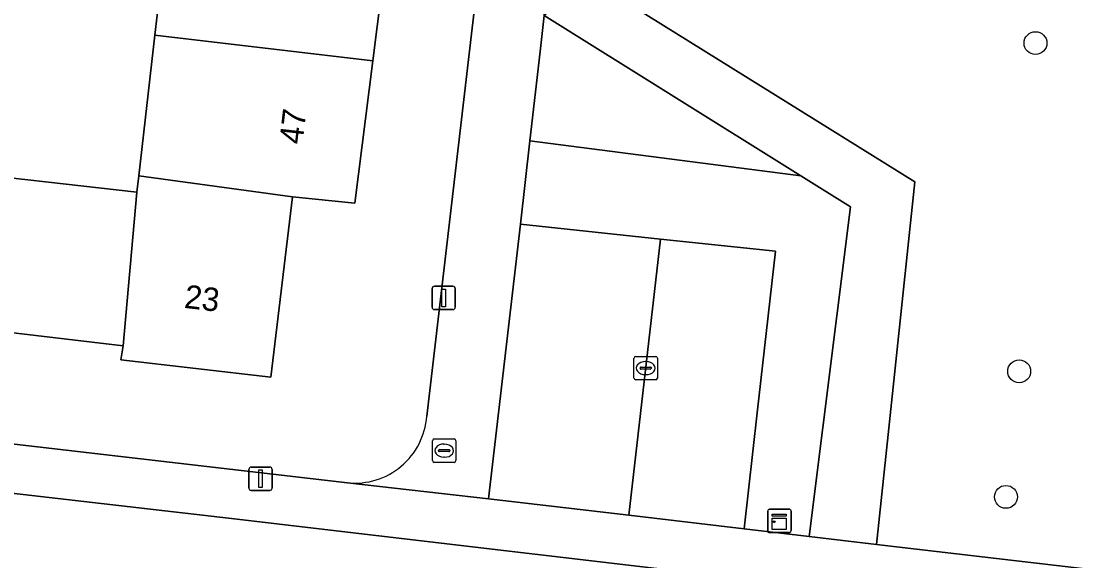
# Model space of a CAD drawing. Extents: x 161241 to 161758, y 384138 to 384885.
# Drawn here: x 161373.53 to 161418.62, y 384429.23 to 384452.33 of the extents above; entities that cross this region are included whole.
import ezdxf

# ---------------------------------------------------------------- set-up
doc = ezdxf.new("R2010")
doc.units = 0
for name, color, linetype in [('IMGEO_Boom', 7, 'Continuous'), ('IMGEO_Brandkraan', 7, 'Continuous'), ('IMGEO_Erf', 7, 'Continuous'), ('IMGEO_Groenvoorziening', 7, 'Continuous'), ('IMGEO_Kast', 7, 'Continuous'), ('IMGEO_Kolk', 7, 'Continuous'), ('IMGEO_Lichtmast', 7, 'Continuous'), ('IMGEO_Pand', 7, 'Continuous'), ('IMGEO_Pand_nummerreeks', 7, 'Continuous'), ('IMGEO_Parkeervlak_open', 7, 'Continuous'), ('IMGEO_Rijbaan_lokaal_open', 7, 'Continuous'), ('IMGEO_Voetpad_open', 7, 'Continuous')]:
    doc.layers.add(name, color=color, linetype=linetype)

msp = doc.modelspace()

# ---------------------------------------------------------------- linework, layer by layer
at = {"layer": 'IMGEO_Boom'}
for centre in [(161416.893, 384451.385), (161416.198, 384437.343), (161415.63, 384431.973)]:
    msp.add_circle(centre, 0.489, dxfattribs=at)
at = {"layer": 'IMGEO_Brandkraan'}
for p, q in [((161391.117, 384433.524), (161391.117, 384434.376)), ((161391.192, 384434.45), (161392.044, 384434.45)), ((161391.605, 384434.23), (161391.63, 384434.23)), ((161392.118, 384434.376), (161392.118, 384433.524)), ((161391.376, 384433.944), (161391.376, 384433.956)), ((161391.814, 384433.907), (161391.416, 384433.907)), ((161391.419, 384433.993), (161391.817, 384433.993)), ((161391.628, 384433.67), (161391.603, 384433.67)), ((161391.86, 384433.956), (161391.86, 384433.944)), ((161392.044, 384433.45), (161391.192, 384433.45))]:
    msp.add_line(p, q, dxfattribs=at)
for points in [[(161391.117, 384433.524), (161391.117, 384434.376)], [(161391.192, 384434.45), (161392.044, 384434.45)], [(161392.118, 384434.376), (161392.118, 384433.524)], [(161392.044, 384433.45), (161391.192, 384433.45)]]:
    msp.add_lwpolyline(points, dxfattribs=at)
for centre, radius, start, end in [((161391.194, 384434.374), 0.0765, 91.552, 178.448), ((161391.194, 384434.374), 0.0765, 91.552, 178.448), ((161392.042, 384434.374), 0.0765, 1.552, 88.448), ((161392.042, 384434.374), 0.0765, 1.552, 88.448), ((161391.416, 384433.953), 0.0403, 85.8775, 175.7526), ((161391.413, 384433.943), 0.0366, 178.938, 274.7102), ((161391.817, 384433.95), 0.043, 264.8664, 352.4533), ((161391.821, 384433.955), 0.0386, 1.7309, 96.639), ((161391.194, 384433.526), 0.0765, 181.552, 268.448), ((161391.194, 384433.526), 0.0765, 181.552, 268.448), ((161392.042, 384433.526), 0.0765, 271.552, 358.448), ((161392.042, 384433.526), 0.0765, 271.552, 358.448)]:
    msp.add_arc(centre, radius, start, end, dxfattribs=at)
for centre, major_axis, ratio, start_param, end_param in [((161391.604, 384433.95), (-0.387, 0.002), 0.722429, 4.712389, 7.853982), ((161391.629, 384433.95), (-0.39, 0.002), 0.717154, 1.570796, 4.712389)]:
    msp.add_ellipse(centre, major_axis=major_axis, ratio=ratio, start_param=start_param, end_param=end_param, dxfattribs=at)
at = {"layer": 'IMGEO_Erf'}
for points in [[(161390.869, 384435.421), (161397.785, 384494.638)], [(161350.003, 384465.226), (161347.677, 384465.495), (161345.413, 384465.757), (161345.447, 384466.051), (161341.804, 384466.297), (161340.159, 384467.275), (161339.305, 384465.833), (161336.535, 384438.485), (161387.488, 384432.576)], [(161369.897, 384445.983), (161378.483, 384445.002), (161378.564, 384445.707), (161379.251, 384451.718), (161379.938, 384457.726)], [(161389.327, 384456.63), (161388.569, 384450.629), (161387.8, 384444.539), (161385.125, 384444.814), (161384.202, 384437.09), (161377.798, 384437.835), (161377.895, 384438.441), (161369.09, 384439.476)]]:
    msp.add_lwpolyline(points, dxfattribs=at)
msp.add_arc((161387.796, 384435.641), 3.081, 264.2615, 355.8975, dxfattribs=at)
at = {"layer": 'IMGEO_Groenvoorziening'}
msp.add_lwpolyline([(161409.377, 384462.778), (161397.9, 384454.084), (161411.738, 384445.455), (161410.62, 384434.912), (161410.092, 384429.939), (161427.439, 384427.904), (161432.833, 384473.658)], dxfattribs=at)
for points in [[(161411.738, 384445.455), (161397.9, 384454.084), (161395.896, 384452.566), (161406.866, 384445.708), (161408.983, 384444.384), (161407.225, 384430.276), (161410.092, 384429.939), (161410.62, 384434.912)], [(161395.896, 384452.566), (161395.721, 384451.026), (161395.284, 384447.211), (161406.866, 384445.708)], [(161406.866, 384445.708), (161395.284, 384447.211), (161394.875, 384443.637), (161400.861, 384443.004), (161405.773, 384442.485), (161404.999, 384435.571), (161404.443, 384430.602), (161407.225, 384430.276), (161408.983, 384444.384)]]:
    msp.add_lwpolyline(points, close=True, dxfattribs=at)
at = {"layer": 'IMGEO_Kast'}
for p, q in [((161405.445, 384430.52), (161405.445, 384431.361)), ((161405.445, 384431.361), (161405.445, 384430.52)), ((161405.52, 384431.445), (161406.361, 384431.445)), ((161406.361, 384431.445), (161405.52, 384431.445)), ((161406.445, 384431.37), (161406.445, 384430.529)), ((161406.445, 384430.529), (161406.445, 384431.37)), ((161406.37, 384430.445), (161405.529, 384430.445)), ((161405.529, 384430.445), (161406.37, 384430.445))]:
    msp.add_line(p, q, dxfattribs=at)
for points in [[(161405.64, 384431.235), (161406.24, 384431.235), (161406.24, 384431.15), (161405.64, 384431.15), (161405.64, 384431.235)], [(161405.64, 384431.06), (161406.24, 384431.06), (161406.24, 384430.571), (161405.64, 384430.571), (161405.64, 384431.06)]]:
    msp.add_lwpolyline(points, dxfattribs=at)
msp.add_circle((161405.724, 384430.909), 0.0377, dxfattribs=at)
for centre, start, end in [((161405.523, 384431.367), 92.4484, 184.2845), ((161405.523, 384431.367), 92.4484, 184.2845), ((161406.367, 384431.367), 2.4484, 94.2845), ((161406.367, 384431.367), 2.4484, 94.2845), ((161405.523, 384430.523), 182.4484, 274.2845), ((161405.523, 384430.523), 182.4484, 274.2845), ((161406.367, 384430.523), 272.4484, 4.2845), ((161406.367, 384430.523), 272.4484, 4.2845)]:
    msp.add_arc(centre, 0.0779, start, end, dxfattribs=at)
at = {"layer": 'IMGEO_Kolk'}
for p, q in [((161399.73, 384437.058), (161399.73, 384437.91)), ((161399.805, 384437.984), (161400.657, 384437.984)), ((161400.218, 384437.764), (161400.243, 384437.764)), ((161400.731, 384437.91), (161400.731, 384437.058)), ((161399.989, 384437.478), (161399.989, 384437.49)), ((161400.427, 384437.441), (161400.029, 384437.441)), ((161400.032, 384437.527), (161400.43, 384437.527)), ((161400.241, 384437.204), (161400.216, 384437.204)), ((161400.473, 384437.49), (161400.473, 384437.478)), ((161400.657, 384436.984), (161399.805, 384436.984))]:
    msp.add_line(p, q, dxfattribs=at)
for points in [[(161399.73, 384437.058), (161399.73, 384437.91)], [(161399.805, 384437.984), (161400.657, 384437.984)], [(161400.731, 384437.91), (161400.731, 384437.058)], [(161400.657, 384436.984), (161399.805, 384436.984)]]:
    msp.add_lwpolyline(points, dxfattribs=at)
for centre, radius, start, end in [((161399.807, 384437.908), 0.0765, 91.552, 178.448), ((161399.807, 384437.908), 0.0765, 91.552, 178.448), ((161400.655, 384437.908), 0.0765, 1.552, 88.448), ((161400.655, 384437.908), 0.0765, 1.552, 88.448), ((161400.029, 384437.487), 0.0403, 85.8775, 175.7526), ((161400.026, 384437.477), 0.0366, 178.938, 274.7102), ((161400.43, 384437.484), 0.043, 264.8664, 352.4533), ((161400.434, 384437.489), 0.0386, 1.7309, 96.639), ((161399.807, 384437.06), 0.0765, 181.552, 268.448), ((161399.807, 384437.06), 0.0765, 181.552, 268.448), ((161400.655, 384437.06), 0.0765, 271.552, 358.448), ((161400.655, 384437.06), 0.0765, 271.552, 358.448)]:
    msp.add_arc(centre, radius, start, end, dxfattribs=at)
for centre, major_axis, ratio, start_param, end_param in [((161400.217, 384437.484), (-0.387, 0.002), 0.722429, 4.712389, 7.853982), ((161400.242, 384437.484), (-0.39, 0.002), 0.717154, 1.570796, 4.712389)]:
    msp.add_ellipse(centre, major_axis=major_axis, ratio=ratio, start_param=start_param, end_param=end_param, dxfattribs=at)
at = {"layer": 'IMGEO_Lichtmast'}
for p, q in [((161391.097, 384440.082), (161391.097, 384440.882)), ((161391.097, 384440.882), (161391.097, 384440.082)), ((161391.197, 384440.982), (161391.987, 384440.982)), ((161391.987, 384440.982), (161391.197, 384440.982)), ((161392.087, 384440.882), (161392.087, 384440.082)), ((161392.087, 384440.082), (161392.087, 384440.882)), ((161391.987, 384439.982), (161391.197, 384439.982)), ((161391.197, 384439.982), (161391.987, 384439.982)), ((161383.267, 384432.349), (161383.267, 384433.149)), ((161383.267, 384433.149), (161383.267, 384432.349)), ((161383.367, 384433.249), (161384.157, 384433.249)), ((161384.157, 384433.249), (161383.367, 384433.249)), ((161384.257, 384433.149), (161384.257, 384432.349)), ((161384.257, 384432.349), (161384.257, 384433.149)), ((161384.157, 384432.249), (161383.367, 384432.249)), ((161383.367, 384432.249), (161384.157, 384432.249))]:
    msp.add_line(p, q, dxfattribs=at)
for points in [[(161391.517, 384440.857), (161391.667, 384440.857), (161391.667, 384440.107), (161391.517, 384440.107), (161391.517, 384440.857)], [(161383.687, 384433.124), (161383.837, 384433.124), (161383.837, 384432.374), (161383.687, 384432.374), (161383.687, 384433.124)]]:
    msp.add_lwpolyline(points, dxfattribs=at)
for centre, start, end in [((161391.197, 384440.882), 90, 180), ((161391.197, 384440.882), 90, 180), ((161391.987, 384440.882), 0, 90), ((161391.987, 384440.882), 360, 90), ((161391.197, 384440.082), 180, 270), ((161391.197, 384440.082), 180, 270), ((161391.987, 384440.082), 270, 0), ((161391.987, 384440.082), 270, 0), ((161383.367, 384433.149), 90, 180), ((161383.367, 384433.149), 90, 180), ((161384.157, 384433.149), 0, 90), ((161384.157, 384433.149), 360, 90), ((161383.367, 384432.349), 180, 270), ((161383.367, 384432.349), 180, 270), ((161384.157, 384432.349), 270, 0), ((161384.157, 384432.349), 270, 0)]:
    msp.add_arc(centre, 0.1, start, end, dxfattribs=at)
at = {"layer": 'IMGEO_Pand'}
for points in [[(161379.938, 384457.726), (161379.251, 384451.718), (161388.569, 384450.629), (161389.327, 384456.63)], [(161378.564, 384445.707), (161385.125, 384444.814), (161387.8, 384444.539), (161388.569, 384450.629), (161379.251, 384451.718)], [(161377.895, 384438.441), (161378.483, 384445.002), (161369.897, 384445.983), (161369.09, 384439.476)], [(161378.483, 384445.002), (161377.895, 384438.441), (161377.798, 384437.835), (161384.202, 384437.09), (161385.125, 384444.814), (161378.564, 384445.707)]]:
    msp.add_lwpolyline(points, close=True, dxfattribs=at)
at = {"layer": 'IMGEO_Parkeervlak_open'}
msp.add_lwpolyline([(161399.514, 384431.19), (161404.443, 384430.602), (161404.999, 384435.571), (161405.773, 384442.485), (161400.861, 384443.004)], close=True, dxfattribs=at)
at = {"layer": 'IMGEO_Rijbaan_lokaal_open'}
msp.add_lwpolyline([(161399.514, 384431.19), (161400.861, 384443.004), (161394.875, 384443.637), (161393.511, 384431.885)], close=True, dxfattribs=at)
msp.add_lwpolyline([(161346.013, 384430.497), (161367.914, 384427.91), (161385.608, 384425.915), (161386.646, 384425.81), (161397.686, 384424.536), (161399.676, 384424.254), (161401.363, 384424.054), (161401.922, 384428.768), (161382.402, 384431.06), (161336.257, 384436.376)], dxfattribs=at)
at = {"layer": 'IMGEO_Voetpad_open'}
for points in [[(161387.488, 384432.576), (161393.511, 384431.885), (161394.875, 384443.637), (161395.284, 384447.211), (161395.721, 384451.026), (161395.896, 384452.566), (161396.451, 384457.375), (161396.553, 384458.256), (161401.111, 384497.3)], [(161397.785, 384494.638), (161390.869, 384435.421)]]:
    msp.add_lwpolyline(points, dxfattribs=at)
msp.add_lwpolyline([(161427.439, 384427.904), (161410.092, 384429.939), (161407.225, 384430.276), (161404.443, 384430.602), (161399.514, 384431.19), (161393.511, 384431.885), (161387.488, 384432.576), (161336.535, 384438.485), (161336.257, 384436.376), (161382.402, 384431.06), (161401.922, 384428.768), (161404.653, 384428.447), (161443.686, 384423.864), (161452.639, 384422.825), (161455.361, 384422.51), (161500, 384417.331), (161516.896, 384415.376), (161517.124, 384417.504), (161500, 384419.47), (161446.947, 384425.581), (161440.852, 384426.331)], close=True, dxfattribs=at)
msp.add_arc((161387.796, 384435.641), 3.081, 264.2615, 355.8975, dxfattribs=at)

# ---------------------------------------------------------------- texts
at = {"layer": 'IMGEO_Pand_nummerreeks'}
for s, rotation, p in [('47', 83.3157, (161385.555, 384447.029)), ('23', 353.3644, (161380.47, 384440.061))]:
    msp.add_text(s, height=1, rotation=rotation, dxfattribs=at).set_placement(p)

doc.saveas('drawing.dxf')
